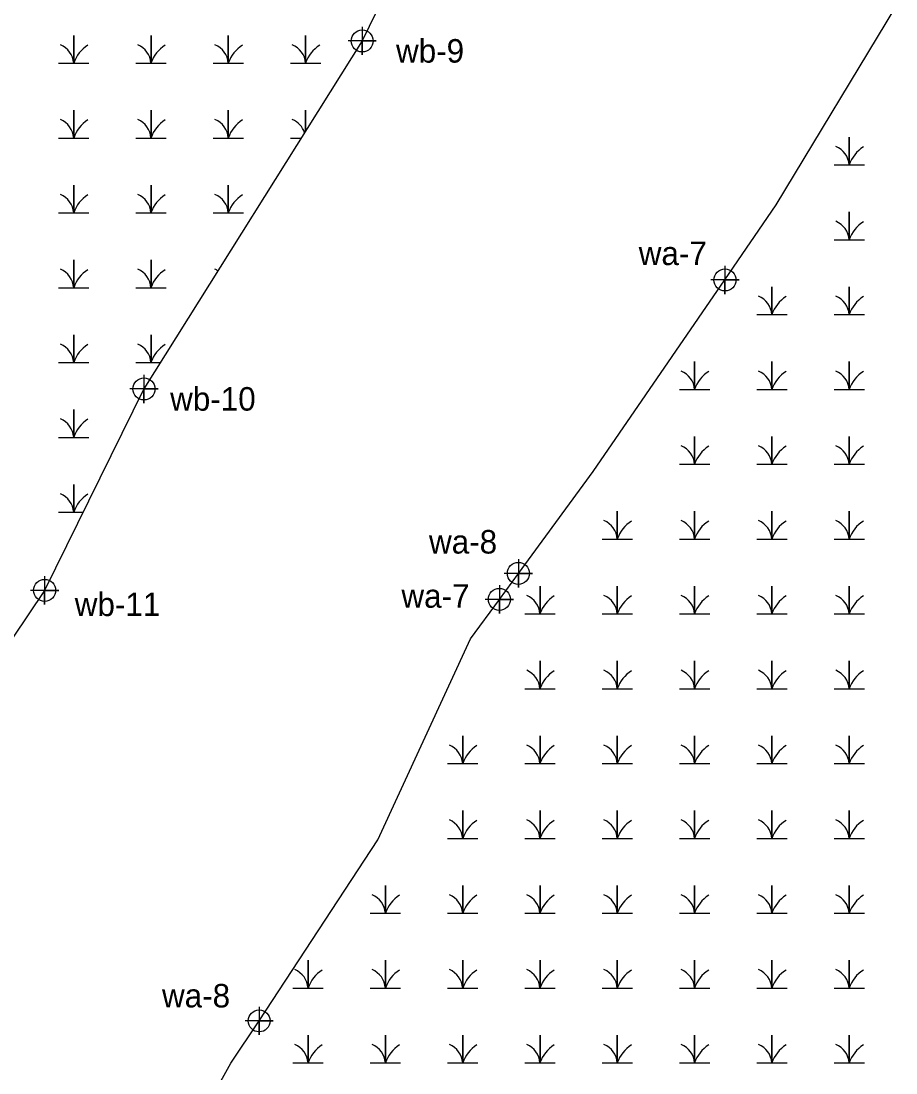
# Model space of a CAD drawing. Extents: x 2379288 to 2381905, y 330670 to 333511.
# Drawn here: x 2380029.7 to 2380215.9, y 331753.1 to 331976.8 of the extents above; entities that cross this region are included whole.
import ezdxf

# ---------------------------------------------------------------- set-up
doc = ezdxf.new("R2010")
doc.units = 0
for name, color, linetype in [('Exist Environmental Wetland Boundary', 7, 'Continuous'), ('Exist Environmental Wetland Boundary Cogo Number', 7, 'Continuous'), ('Exist Environmental Wetland Boundary Cogo Point CELL', 7, 'Continuous'), ('Exist Hydro Swamp or Marsh', 7, 'Continuous')]:
    doc.layers.add(name, color=color, linetype=linetype)

msp = doc.modelspace()

# ---------------------------------------------------------------- linework, layer by layer
at = {"layer": 'Exist Environmental Wetland Boundary'}
for points in [[(2380130.29, 332029.9), (2380102.32, 331972.59), (2380055.88, 331898.56), (2380034.74, 331855.71), (2379997.28, 331799.99), (2379955.67, 331743.45), (2379938.98, 331697.47), (2379905.07, 331626.66), (2379844.93, 331533.46), (2379815.25, 331542.18), (2379791.29, 331555.41), (2379761.99, 331575.7), (2379733.64, 331601.14), (2379721.48, 331609.71)], [(2379969.53, 331242.58), (2379951.18, 331271.07), (2379927.68, 331301.39), (2379890.44, 331365.66), (2379892.64, 331447.19), (2379906.39, 331470.26), (2379921.41, 331493.05), (2379928.27, 331503.45), (2379949.79, 331537.93), (2379979.44, 331586.24), (2380001.81, 331628.04), (2380020.7, 331661.36), (2380049.79, 331711.02), (2380074.34, 331755.11), (2380080.4, 331764.13), (2380105.64, 331802.62), (2380125.36, 331845.41), (2380131.51, 331853.8), (2380135.55, 331859.31), (2380151.44, 331880.98), (2380179.52, 331921.73), (2380190.43, 331937.74), (2380215.91, 331979.8)]]:
    msp.add_lwpolyline(points, dxfattribs=at)
at = {"layer": 'Exist Environmental Wetland Boundary Cogo Point CELL'}
for points in [[(2380102.32, 331975.59), (2380102.32, 331969.59), (2380102.32, 331972.59), (2380105.32, 331972.59), (2380099.32, 331972.59)], [(2380179.52, 331924.73), (2380179.52, 331918.73), (2380179.52, 331921.73), (2380182.52, 331921.73), (2380176.52, 331921.73)], [(2380055.88, 331901.56), (2380055.88, 331895.56), (2380055.88, 331898.56), (2380058.88, 331898.56), (2380052.88, 331898.56)], [(2380135.55, 331862.31), (2380135.55, 331856.31), (2380135.55, 331859.31), (2380138.55, 331859.31), (2380132.55, 331859.31)], [(2380034.74, 331858.71), (2380034.74, 331852.71), (2380034.74, 331855.71), (2380037.74, 331855.71), (2380031.74, 331855.71)], [(2380131.51, 331856.8), (2380131.51, 331850.8), (2380131.51, 331853.8), (2380134.51, 331853.8), (2380128.51, 331853.8)], [(2380080.4, 331767.13), (2380080.4, 331761.13), (2380080.4, 331764.13), (2380083.4, 331764.13), (2380077.4, 331764.13)]]:
    msp.add_lwpolyline(points, dxfattribs=at)
for centre in [(2380102.32, 331972.59), (2380179.52, 331921.73), (2380055.88, 331898.56), (2380135.55, 331859.31), (2380034.74, 331855.71), (2380131.51, 331853.8), (2380080.4, 331764.13)]:
    msp.add_circle(centre, 2.34, dxfattribs=at)
at = {"layer": 'Exist Hydro Swamp or Marsh'}
msp.add_line((2380087.06, 331951.93), (2380089.36, 331951.93), dxfattribs=at)
for points in [[(2380037.7, 331967.85), (2380040.93, 331967.85), (2380040.93, 331973.76), (2380040.93, 331967.85), (2380044.15, 331967.85)], [(2380054.15, 331967.85), (2380057.38, 331967.85), (2380057.38, 331973.76), (2380057.38, 331967.85), (2380060.6, 331967.85)], [(2380070.6, 331967.85), (2380073.83, 331967.85), (2380073.83, 331973.76), (2380073.83, 331967.85), (2380077.06, 331967.85)], [(2380087.06, 331967.85), (2380090.28, 331967.85), (2380090.28, 331973.76), (2380090.28, 331967.85), (2380093.51, 331967.85)], [(2380037.7, 331951.93), (2380040.93, 331951.93), (2380040.93, 331957.85), (2380040.93, 331951.93), (2380044.15, 331951.93)], [(2380054.15, 331951.93), (2380057.38, 331951.93), (2380057.38, 331957.85), (2380057.38, 331951.93), (2380060.6, 331951.93)], [(2380070.6, 331951.93), (2380073.83, 331951.93), (2380073.83, 331957.85), (2380073.83, 331951.93), (2380077.06, 331951.93)], [(2380090.28, 331953.4), (2380090.28, 331957.85), (2380090.28, 331953.4)], [(2380202.74, 331946.2), (2380205.97, 331946.2), (2380205.97, 331952.12), (2380205.97, 331946.2), (2380209.19, 331946.2)], [(2380037.7, 331936.01), (2380040.93, 331936.01), (2380040.93, 331941.93), (2380040.93, 331936.01), (2380044.15, 331936.01)], [(2380054.15, 331936.01), (2380057.38, 331936.01), (2380057.38, 331941.93), (2380057.38, 331936.01), (2380060.6, 331936.01)], [(2380070.6, 331936.01), (2380073.83, 331936.01), (2380073.83, 331941.93), (2380073.83, 331936.01), (2380077.06, 331936.01)], [(2380202.74, 331930.28), (2380205.97, 331930.28), (2380205.97, 331936.2), (2380205.97, 331930.28), (2380209.19, 331930.28)], [(2380037.7, 331920.09), (2380040.93, 331920.09), (2380040.93, 331926.01), (2380040.93, 331920.09), (2380044.15, 331920.09)], [(2380054.15, 331920.09), (2380057.38, 331920.09), (2380057.38, 331926.01), (2380057.38, 331920.09), (2380060.6, 331920.09)], [(2380186.29, 331914.36), (2380189.51, 331914.36), (2380189.51, 331920.28), (2380189.51, 331914.36), (2380192.74, 331914.36)], [(2380202.74, 331914.36), (2380205.97, 331914.36), (2380205.97, 331920.28), (2380205.97, 331914.36), (2380209.19, 331914.36)], [(2380037.7, 331904.18), (2380040.93, 331904.18), (2380040.93, 331910.09), (2380040.93, 331904.18), (2380044.15, 331904.18)], [(2380054.15, 331904.18), (2380057.38, 331904.18), (2380057.38, 331910.09), (2380057.38, 331904.18), (2380059.4, 331904.18)], [(2380169.84, 331898.45), (2380173.06, 331898.45), (2380173.06, 331904.36), (2380173.06, 331898.45), (2380176.29, 331898.45)], [(2380186.29, 331898.45), (2380189.51, 331898.45), (2380189.51, 331904.36), (2380189.51, 331898.45), (2380192.74, 331898.45)], [(2380202.74, 331898.45), (2380205.97, 331898.45), (2380205.97, 331904.36), (2380205.97, 331898.45), (2380209.19, 331898.45)], [(2380037.7, 331888.26), (2380040.93, 331888.26), (2380040.93, 331894.18), (2380040.93, 331888.26), (2380044.15, 331888.26)], [(2380169.84, 331882.53), (2380173.06, 331882.53), (2380173.06, 331888.45), (2380173.06, 331882.53), (2380176.29, 331882.53)], [(2380186.29, 331882.53), (2380189.51, 331882.53), (2380189.51, 331888.45), (2380189.51, 331882.53), (2380192.74, 331882.53)], [(2380202.74, 331882.53), (2380205.97, 331882.53), (2380205.97, 331888.45), (2380205.97, 331882.53), (2380209.19, 331882.53)], [(2380037.7, 331872.34), (2380040.93, 331872.34), (2380040.93, 331878.26), (2380040.93, 331872.34), (2380042.94, 331872.34)], [(2380153.39, 331866.61), (2380156.61, 331866.61), (2380156.61, 331872.53), (2380156.61, 331866.61), (2380159.84, 331866.61)], [(2380169.84, 331866.61), (2380173.06, 331866.61), (2380173.06, 331872.53), (2380173.06, 331866.61), (2380176.29, 331866.61)], [(2380186.29, 331866.61), (2380189.51, 331866.61), (2380189.51, 331872.53), (2380189.51, 331866.61), (2380192.74, 331866.61)], [(2380202.74, 331866.61), (2380205.97, 331866.61), (2380205.97, 331872.53), (2380205.97, 331866.61), (2380209.19, 331866.61)], [(2380136.93, 331850.69), (2380140.16, 331850.69), (2380140.16, 331856.61), (2380140.16, 331850.69), (2380143.39, 331850.69)], [(2380153.39, 331850.69), (2380156.61, 331850.69), (2380156.61, 331856.61), (2380156.61, 331850.69), (2380159.84, 331850.69)], [(2380169.84, 331850.69), (2380173.06, 331850.69), (2380173.06, 331856.61), (2380173.06, 331850.69), (2380176.29, 331850.69)], [(2380186.29, 331850.69), (2380189.51, 331850.69), (2380189.51, 331856.61), (2380189.51, 331850.69), (2380192.74, 331850.69)], [(2380202.74, 331850.69), (2380205.97, 331850.69), (2380205.97, 331856.61), (2380205.97, 331850.69), (2380209.19, 331850.69)], [(2380136.93, 331834.77), (2380140.16, 331834.77), (2380140.16, 331840.69), (2380140.16, 331834.77), (2380143.39, 331834.77)], [(2380153.39, 331834.77), (2380156.61, 331834.77), (2380156.61, 331840.69), (2380156.61, 331834.77), (2380159.84, 331834.77)], [(2380169.84, 331834.77), (2380173.06, 331834.77), (2380173.06, 331840.69), (2380173.06, 331834.77), (2380176.29, 331834.77)], [(2380186.29, 331834.77), (2380189.51, 331834.77), (2380189.51, 331840.69), (2380189.51, 331834.77), (2380192.74, 331834.77)], [(2380202.74, 331834.77), (2380205.97, 331834.77), (2380205.97, 331840.69), (2380205.97, 331834.77), (2380209.19, 331834.77)], [(2380120.48, 331818.86), (2380123.71, 331818.86), (2380123.71, 331824.77), (2380123.71, 331818.86), (2380126.93, 331818.86)], [(2380136.93, 331818.86), (2380140.16, 331818.86), (2380140.16, 331824.77), (2380140.16, 331818.86), (2380143.39, 331818.86)], [(2380153.39, 331818.86), (2380156.61, 331818.86), (2380156.61, 331824.77), (2380156.61, 331818.86), (2380159.84, 331818.86)], [(2380169.84, 331818.86), (2380173.06, 331818.86), (2380173.06, 331824.77), (2380173.06, 331818.86), (2380176.29, 331818.86)], [(2380186.29, 331818.86), (2380189.51, 331818.86), (2380189.51, 331824.77), (2380189.51, 331818.86), (2380192.74, 331818.86)], [(2380202.74, 331818.86), (2380205.97, 331818.86), (2380205.97, 331824.77), (2380205.97, 331818.86), (2380209.19, 331818.86)], [(2380120.48, 331802.94), (2380123.71, 331802.94), (2380123.71, 331808.86), (2380123.71, 331802.94), (2380126.93, 331802.94)], [(2380136.93, 331802.94), (2380140.16, 331802.94), (2380140.16, 331808.86), (2380140.16, 331802.94), (2380143.39, 331802.94)], [(2380153.39, 331802.94), (2380156.61, 331802.94), (2380156.61, 331808.86), (2380156.61, 331802.94), (2380159.84, 331802.94)], [(2380169.84, 331802.94), (2380173.06, 331802.94), (2380173.06, 331808.86), (2380173.06, 331802.94), (2380176.29, 331802.94)], [(2380186.29, 331802.94), (2380189.51, 331802.94), (2380189.51, 331808.86), (2380189.51, 331802.94), (2380192.74, 331802.94)], [(2380202.74, 331802.94), (2380205.97, 331802.94), (2380205.97, 331808.86), (2380205.97, 331802.94), (2380209.19, 331802.94)], [(2380104.03, 331787.02), (2380107.26, 331787.02), (2380107.26, 331792.94), (2380107.26, 331787.02), (2380110.48, 331787.02)], [(2380120.48, 331787.02), (2380123.71, 331787.02), (2380123.71, 331792.94), (2380123.71, 331787.02), (2380126.93, 331787.02)], [(2380136.93, 331787.02), (2380140.16, 331787.02), (2380140.16, 331792.94), (2380140.16, 331787.02), (2380143.39, 331787.02)], [(2380153.39, 331787.02), (2380156.61, 331787.02), (2380156.61, 331792.94), (2380156.61, 331787.02), (2380159.84, 331787.02)], [(2380169.84, 331787.02), (2380173.06, 331787.02), (2380173.06, 331792.94), (2380173.06, 331787.02), (2380176.29, 331787.02)], [(2380186.29, 331787.02), (2380189.51, 331787.02), (2380189.51, 331792.94), (2380189.51, 331787.02), (2380192.74, 331787.02)], [(2380202.74, 331787.02), (2380205.97, 331787.02), (2380205.97, 331792.94), (2380205.97, 331787.02), (2380209.19, 331787.02)], [(2380087.58, 331771.1), (2380090.81, 331771.1), (2380090.81, 331777.02), (2380090.81, 331771.1), (2380094.03, 331771.1)], [(2380104.03, 331771.1), (2380107.26, 331771.1), (2380107.26, 331777.02), (2380107.26, 331771.1), (2380110.48, 331771.1)], [(2380120.48, 331771.1), (2380123.71, 331771.1), (2380123.71, 331777.02), (2380123.71, 331771.1), (2380126.93, 331771.1)], [(2380136.93, 331771.1), (2380140.16, 331771.1), (2380140.16, 331777.02), (2380140.16, 331771.1), (2380143.39, 331771.1)], [(2380153.39, 331771.1), (2380156.61, 331771.1), (2380156.61, 331777.02), (2380156.61, 331771.1), (2380159.84, 331771.1)], [(2380169.84, 331771.1), (2380173.06, 331771.1), (2380173.06, 331777.02), (2380173.06, 331771.1), (2380176.29, 331771.1)], [(2380186.29, 331771.1), (2380189.51, 331771.1), (2380189.51, 331777.02), (2380189.51, 331771.1), (2380192.74, 331771.1)], [(2380202.74, 331771.1), (2380205.97, 331771.1), (2380205.97, 331777.02), (2380205.97, 331771.1), (2380209.19, 331771.1)], [(2380087.58, 331755.19), (2380090.81, 331755.19), (2380090.81, 331761.1), (2380090.81, 331755.19), (2380094.03, 331755.19)], [(2380104.03, 331755.19), (2380107.26, 331755.19), (2380107.26, 331761.1), (2380107.26, 331755.19), (2380110.48, 331755.19)], [(2380120.48, 331755.19), (2380123.71, 331755.19), (2380123.71, 331761.1), (2380123.71, 331755.19), (2380126.93, 331755.19)], [(2380136.93, 331755.19), (2380140.16, 331755.19), (2380140.16, 331761.1), (2380140.16, 331755.19), (2380143.39, 331755.19)], [(2380153.39, 331755.19), (2380156.61, 331755.19), (2380156.61, 331761.1), (2380156.61, 331755.19), (2380159.84, 331755.19)], [(2380169.84, 331755.19), (2380173.06, 331755.19), (2380173.06, 331761.1), (2380173.06, 331755.19), (2380176.29, 331755.19)], [(2380186.29, 331755.19), (2380189.51, 331755.19), (2380189.51, 331761.1), (2380189.51, 331755.19), (2380192.74, 331755.19)], [(2380202.74, 331755.19), (2380205.97, 331755.19), (2380205.97, 331761.1), (2380205.97, 331755.19), (2380209.19, 331755.19)]]:
    msp.add_lwpolyline(points, dxfattribs=at)
for centre, radius, start, end in [((2380036.33, 331967.51), 4.61, 4.1403, 67.535), ((2380047.77, 331965.57), 7.21, 122.1274, 161.6222), ((2380052.78, 331967.51), 4.61, 4.1403, 67.535), ((2380064.22, 331965.57), 7.21, 122.1274, 161.6222), ((2380069.23, 331967.51), 4.61, 4.1403, 67.535), ((2380080.67, 331965.57), 7.21, 122.1274, 161.6222), ((2380085.68, 331967.51), 4.61, 4.1403, 67.535), ((2380097.12, 331965.57), 7.21, 122.1274, 161.6222), ((2380036.33, 331951.6), 4.61, 4.1403, 67.535), ((2380047.77, 331949.66), 7.21, 122.1274, 161.6222), ((2380052.78, 331951.6), 4.61, 4.1403, 67.535), ((2380064.22, 331949.66), 7.21, 122.1274, 161.6222), ((2380069.23, 331951.6), 4.61, 4.1403, 67.535), ((2380080.67, 331949.66), 7.21, 122.1274, 161.6222), ((2380085.68, 331951.6), 4.61, 18.3297, 67.535), ((2380201.37, 331945.87), 4.61, 4.1403, 67.535), ((2380212.81, 331943.93), 7.21, 122.1274, 161.6222), ((2380036.33, 331935.68), 4.61, 4.1403, 67.535), ((2380047.77, 331933.74), 7.21, 122.1274, 161.6222), ((2380052.78, 331935.68), 4.61, 4.1403, 67.535), ((2380064.22, 331933.74), 7.21, 122.1274, 161.6222), ((2380069.23, 331935.68), 4.61, 4.1403, 67.535), ((2380080.67, 331933.74), 7.21, 122.1274, 161.6222), ((2380201.37, 331929.95), 4.61, 4.1403, 67.535), ((2380212.81, 331928.01), 7.21, 122.1274, 161.6222), ((2380036.33, 331919.76), 4.61, 4.1403, 67.535), ((2380047.77, 331917.82), 7.21, 122.1274, 161.6222), ((2380052.78, 331919.76), 4.61, 4.1403, 67.535), ((2380064.22, 331917.82), 7.21, 122.1274, 161.6222), ((2380069.23, 331919.76), 4.61, 58.4508, 67.535), ((2380184.91, 331914.03), 4.61, 4.1403, 67.535), ((2380196.35, 331912.09), 7.21, 122.1274, 161.6222), ((2380201.37, 331914.03), 4.61, 4.1403, 67.535), ((2380212.81, 331912.09), 7.21, 122.1274, 161.6222), ((2380036.33, 331903.84), 4.61, 4.1403, 67.535), ((2380047.77, 331901.9), 7.21, 122.1274, 161.6222), ((2380052.78, 331903.84), 4.61, 4.1403, 67.535), ((2380064.22, 331901.9), 7.21, 122.1274, 161.6222), ((2380168.46, 331898.11), 4.61, 4.1403, 67.535), ((2380179.9, 331896.17), 7.21, 122.1274, 161.6222), ((2380184.91, 331898.11), 4.61, 4.1403, 67.535), ((2380196.35, 331896.17), 7.21, 122.1274, 161.6222), ((2380201.37, 331898.11), 4.61, 4.1403, 67.535), ((2380212.81, 331896.17), 7.21, 122.1274, 161.6222), ((2380036.33, 331887.93), 4.61, 4.1403, 67.535), ((2380047.77, 331885.99), 7.21, 122.1274, 161.6222), ((2380168.46, 331882.19), 4.61, 4.1403, 67.535), ((2380179.9, 331880.26), 7.21, 122.1274, 161.6222), ((2380184.91, 331882.19), 4.61, 4.1403, 67.535), ((2380196.35, 331880.26), 7.21, 122.1274, 161.6222), ((2380201.37, 331882.19), 4.61, 4.1403, 67.535), ((2380212.81, 331880.26), 7.21, 122.1274, 161.6222), ((2380036.33, 331872.01), 4.61, 4.1403, 67.535), ((2380047.77, 331870.07), 7.21, 122.1274, 161.6222), ((2380152.01, 331866.28), 4.61, 4.1403, 67.535), ((2380163.45, 331864.34), 7.21, 122.1274, 161.6222), ((2380168.46, 331866.28), 4.61, 4.1403, 67.535), ((2380179.9, 331864.34), 7.21, 122.1274, 161.6222), ((2380184.91, 331866.28), 4.61, 4.1403, 67.535), ((2380196.35, 331864.34), 7.21, 122.1274, 161.6222), ((2380201.37, 331866.28), 4.61, 4.1403, 67.535), ((2380212.81, 331864.34), 7.21, 122.1274, 161.6222), ((2380135.56, 331850.36), 4.61, 4.1403, 67.535), ((2380147, 331848.42), 7.21, 122.1274, 161.6222), ((2380152.01, 331850.36), 4.61, 4.1403, 67.535), ((2380163.45, 331848.42), 7.21, 122.1274, 161.6222), ((2380168.46, 331850.36), 4.61, 4.1403, 67.535), ((2380179.9, 331848.42), 7.21, 122.1274, 161.6222), ((2380184.91, 331850.36), 4.61, 4.1403, 67.535), ((2380196.35, 331848.42), 7.21, 122.1274, 161.6222), ((2380201.37, 331850.36), 4.61, 4.1403, 67.535), ((2380212.81, 331848.42), 7.21, 122.1274, 161.6222), ((2380135.56, 331834.44), 4.61, 4.1403, 67.535), ((2380147, 331832.5), 7.21, 122.1274, 161.6222), ((2380152.01, 331834.44), 4.61, 4.1403, 67.535), ((2380163.45, 331832.5), 7.21, 122.1274, 161.6222), ((2380168.46, 331834.44), 4.61, 4.1403, 67.535), ((2380179.9, 331832.5), 7.21, 122.1274, 161.6222), ((2380184.91, 331834.44), 4.61, 4.1403, 67.535), ((2380196.35, 331832.5), 7.21, 122.1274, 161.6222), ((2380201.37, 331834.44), 4.61, 4.1403, 67.535), ((2380212.81, 331832.5), 7.21, 122.1274, 161.6222), ((2380119.11, 331818.52), 4.61, 4.1403, 67.535), ((2380130.55, 331816.58), 7.21, 122.1274, 161.6222), ((2380135.56, 331818.52), 4.61, 4.1403, 67.535), ((2380147, 331816.58), 7.21, 122.1274, 161.6222), ((2380152.01, 331818.52), 4.61, 4.1403, 67.535), ((2380163.45, 331816.58), 7.21, 122.1274, 161.6222), ((2380168.46, 331818.52), 4.61, 4.1403, 67.535), ((2380179.9, 331816.58), 7.21, 122.1274, 161.6222), ((2380184.91, 331818.52), 4.61, 4.1403, 67.535), ((2380196.35, 331816.58), 7.21, 122.1274, 161.6222), ((2380201.37, 331818.52), 4.61, 4.1403, 67.535), ((2380212.81, 331816.58), 7.21, 122.1274, 161.6222), ((2380119.11, 331802.61), 4.61, 4.1403, 67.535), ((2380130.55, 331800.67), 7.21, 122.1274, 161.6222), ((2380135.56, 331802.61), 4.61, 4.1403, 67.535), ((2380147, 331800.67), 7.21, 122.1274, 161.6222), ((2380152.01, 331802.61), 4.61, 4.1403, 67.535), ((2380163.45, 331800.67), 7.21, 122.1274, 161.6222), ((2380168.46, 331802.61), 4.61, 4.1403, 67.535), ((2380179.9, 331800.67), 7.21, 122.1274, 161.6222), ((2380184.91, 331802.61), 4.61, 4.1403, 67.535), ((2380196.35, 331800.67), 7.21, 122.1274, 161.6222), ((2380201.37, 331802.61), 4.61, 4.1403, 67.535), ((2380212.81, 331800.67), 7.21, 122.1274, 161.6222), ((2380102.66, 331786.69), 4.61, 4.1403, 67.535), ((2380114.1, 331784.75), 7.21, 122.1274, 161.6222), ((2380119.11, 331786.69), 4.61, 4.1403, 67.535), ((2380130.55, 331784.75), 7.21, 122.1274, 161.6222), ((2380135.56, 331786.69), 4.61, 4.1403, 67.535), ((2380147, 331784.75), 7.21, 122.1274, 161.6222), ((2380152.01, 331786.69), 4.61, 4.1403, 67.535), ((2380163.45, 331784.75), 7.21, 122.1274, 161.6222), ((2380168.46, 331786.69), 4.61, 4.1403, 67.535), ((2380179.9, 331784.75), 7.21, 122.1274, 161.6222), ((2380184.91, 331786.69), 4.61, 4.1403, 67.535), ((2380196.35, 331784.75), 7.21, 122.1274, 161.6222), ((2380201.37, 331786.69), 4.61, 4.1403, 67.535), ((2380212.81, 331784.75), 7.21, 122.1274, 161.6222), ((2380086.21, 331770.77), 4.61, 4.1403, 67.535), ((2380097.65, 331768.83), 7.21, 122.1274, 161.6222), ((2380102.66, 331770.77), 4.61, 4.1403, 67.535), ((2380114.1, 331768.83), 7.21, 122.1274, 161.6222), ((2380119.11, 331770.77), 4.61, 4.1403, 67.535), ((2380130.55, 331768.83), 7.21, 122.1274, 161.6222), ((2380135.56, 331770.77), 4.61, 4.1403, 67.535), ((2380147, 331768.83), 7.21, 122.1274, 161.6222), ((2380152.01, 331770.77), 4.61, 4.1403, 67.535), ((2380163.45, 331768.83), 7.21, 122.1274, 161.6222), ((2380168.46, 331770.77), 4.61, 4.1403, 67.535), ((2380179.9, 331768.83), 7.21, 122.1274, 161.6222), ((2380184.91, 331770.77), 4.61, 4.1403, 67.535), ((2380196.35, 331768.83), 7.21, 122.1274, 161.6222), ((2380201.37, 331770.77), 4.61, 4.1403, 67.535), ((2380212.81, 331768.83), 7.21, 122.1274, 161.6222), ((2380086.21, 331754.85), 4.61, 4.1403, 67.535), ((2380097.65, 331752.91), 7.21, 122.1274, 161.6222), ((2380102.66, 331754.85), 4.61, 4.1403, 67.535), ((2380114.1, 331752.91), 7.21, 122.1274, 161.6222), ((2380119.11, 331754.85), 4.61, 4.1403, 67.535), ((2380130.55, 331752.91), 7.21, 122.1274, 161.6222), ((2380135.56, 331754.85), 4.61, 4.1403, 67.535), ((2380147, 331752.91), 7.21, 122.1274, 161.6222), ((2380152.01, 331754.85), 4.61, 4.1403, 67.535), ((2380163.45, 331752.91), 7.21, 122.1274, 161.6222), ((2380168.46, 331754.85), 4.61, 4.1403, 67.535), ((2380179.9, 331752.91), 7.21, 122.1274, 161.6222), ((2380184.91, 331754.85), 4.61, 4.1403, 67.535), ((2380196.35, 331752.91), 7.21, 122.1274, 161.6222), ((2380201.37, 331754.85), 4.61, 4.1403, 67.535), ((2380212.81, 331752.91), 7.21, 122.1274, 161.6222)]:
    msp.add_arc(centre, radius, start, end, dxfattribs=at)

# ---------------------------------------------------------------- texts
at = {"layer": 'Exist Environmental Wetland Boundary Cogo Number'}
for s, p in [('wb-9', (2380109.52, 331967.97)), ('wa-7', (2380161.17, 331924.9)), ('wb-10', (2380061.45, 331893.94)), ('wa-8', (2380116.54, 331863.54)), ('wb-11', (2380041.15, 331850.25)), ('wa-7', (2380110.67, 331852.01)), ('wa-8', (2380059.72, 331766.99))]:
    msp.add_text(s, height=5, dxfattribs=at).set_placement(p)

doc.saveas('drawing.dxf')
